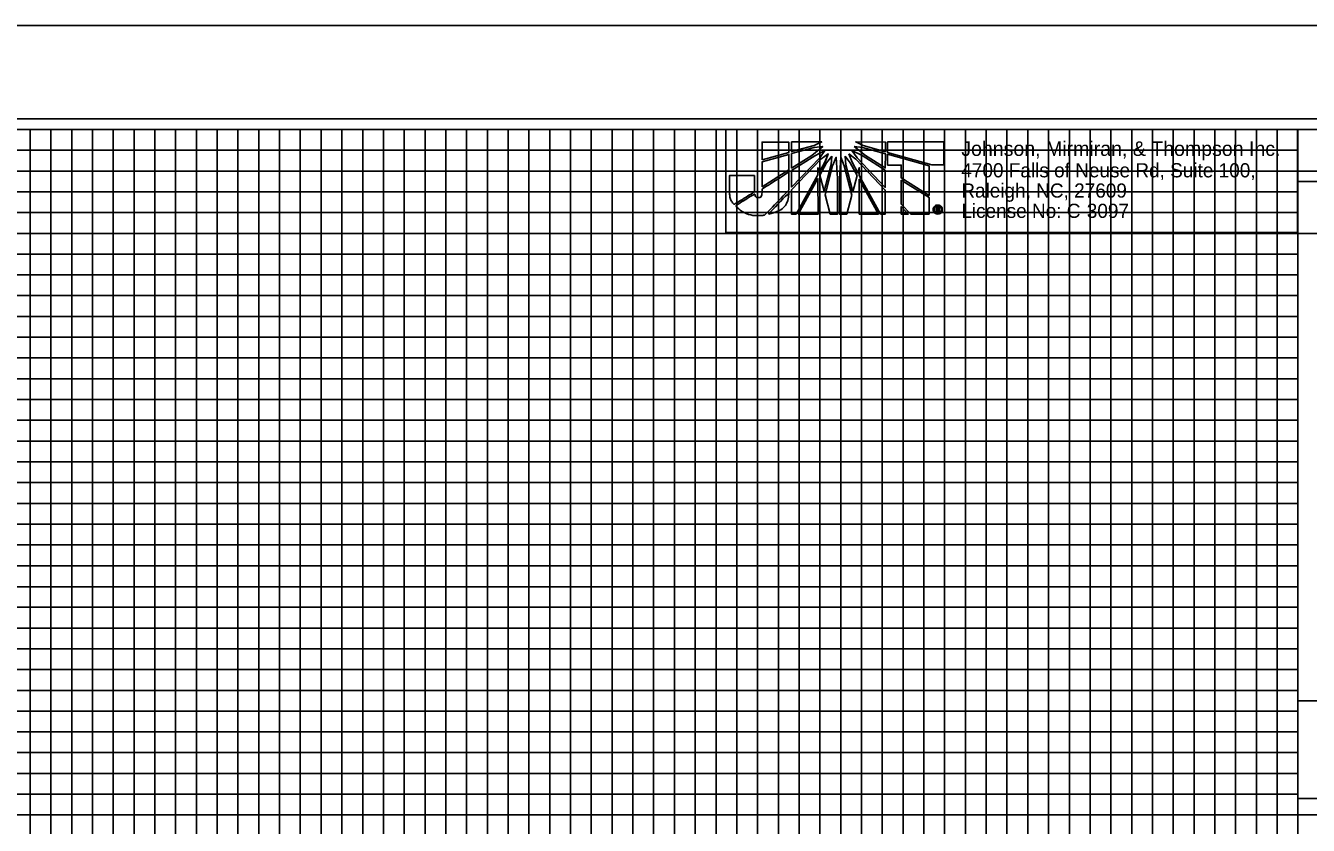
# Model space of a CAD drawing. Extents: x 1623313 to 1628771, y 891211 to 901910.
# Drawn here: x 1624473.9 to 1624782.4, y 901666.9 to 901859.4 of the extents above; entities that cross this region are included whole.
import ezdxf

# ---------------------------------------------------------------- set-up
doc = ezdxf.new("R2010")
doc.units = 0
for name, color, linetype in [('Default', 7, 'Continuous'), ('Prop PHM Black Shape', 7, 'Continuous'), ('Scratch_Level_0', 7, 'Continuous'), ('Sheet Cutting Line CELL', 7, 'Continuous'), ('Sheet DOT Grid CELL', 7, 'Continuous'), ('Sheet Plot Border Inside CELL', 7, 'Continuous'), ('Sheet Plot Border Outside CELL', 7, 'Continuous'), ('Sheet Profile CELL', 7, 'Continuous'), ('Sheet Profile Grid Major CELL', 7, 'Continuous'), ('Sheet Profile Grid Middle CELL', 7, 'Continuous'), ('Sheet Profile Grid Minor CELL', 7, 'Continuous'), ('Sheet Sticker Exception Certification CELL', 7, 'Continuous')]:
    doc.layers.add(name, color=color, linetype=linetype)

msp = doc.modelspace()

# ---------------------------------------------------------------- linework, layer by layer
at = {"layer": 'Default'}
for p, q in [((1624657.46, 901831.41), (1624651.03, 901831.4)), ((1624651.03, 901831.4), (1624651.03, 901827.13)), ((1624657.47, 901828.92), (1624657.46, 901831.41)), ((1624665.38, 901831.45), (1624658.13, 901831.44)), ((1624658.13, 901831.44), (1624658.13, 901829.14)), ((1624663.53, 901830.63), (1624665.38, 901831.45)), ((1624680.71, 901831.43), (1624673.57, 901831.45)), ((1624673.57, 901831.45), (1624675.38, 901830.61)), ((1624680.71, 901829.11), (1624680.71, 901831.43)), ((1624694.74, 901831.47), (1624681.21, 901831.46)), ((1624681.21, 901831.46), (1624681.21, 901828.97)), ((1624694.75, 901825.93), (1624694.74, 901831.47)), ((1624651.03, 901827.13), (1624657.47, 901828.92)), ((1624657.47, 901828.46), (1624651.03, 901826.64)), ((1624657.47, 901824.73), (1624657.47, 901828.46)), ((1624658.13, 901829.14), (1624663.53, 901830.63)), ((1624663.53, 901830.13), (1624658.14, 901828.64)), ((1624658.14, 901828.64), (1624658.14, 901825.15)), ((1624658.14, 901825.15), (1624662.97, 901828.22)), ((1624663.71, 901828.14), (1624658.14, 901824.59)), ((1624662.97, 901828.22), (1624665.63, 901830.38)), ((1624665.63, 901830.38), (1624663.53, 901830.13)), ((1624666.16, 901829.39), (1624663.71, 901828.14)), ((1624664.92, 901827.64), (1624666.16, 901829.39)), ((1624666.91, 901828.61), (1624665.2, 901827.29)), ((1624666.12, 901826.55), (1624666.91, 901828.61)), ((1624667.83, 901828.04), (1624666.56, 901826.4)), ((1624667.65, 901826.05), (1624667.83, 901828.04)), ((1624670.99, 901828.04), (1624671.2, 901825.98)), ((1624672.23, 901826.41), (1624670.99, 901828.04)), ((1624671.9, 901828.62), (1624672.69, 901826.56)), ((1624673.61, 901827.3), (1624671.9, 901828.62)), ((1624672.65, 901829.39), (1624673.9, 901827.62)), ((1624675.14, 901828.15), (1624672.65, 901829.39)), ((1624673.21, 901830.39), (1624675.91, 901828.18)), ((1624675.2, 901830.14), (1624673.21, 901830.39)), ((1624680.67, 901824.64), (1624675.14, 901828.15)), ((1624680.71, 901828.62), (1624675.2, 901830.14)), ((1624675.38, 901830.61), (1624680.71, 901829.11)), ((1624675.91, 901828.18), (1624680.67, 901825.21)), ((1624680.67, 901825.21), (1624680.71, 901828.62)), ((1624681.21, 901828.97), (1624681.21, 901828.9)), ((1624681.21, 901828.9), (1624691.87, 901825.93)), ((1624681.21, 901828.52), (1624681.21, 901828.48)), ((1624691.19, 901825.68), (1624681.21, 901828.52)), ((1624681.21, 901828.48), (1624681.22, 901825.88)), ((1624651.03, 901826.64), (1624651.04, 901820.64)), ((1624651.04, 901820.64), (1624657.47, 901824.73)), ((1624658.14, 901820.58), (1624664.92, 901827.64)), ((1624665.2, 901827.29), (1624658.14, 901819.9)), ((1624664.46, 901823.57), (1624664.46, 901825.26)), ((1624664.46, 901825.26), (1624664.78, 901824.1)), ((1624664.78, 901824.1), (1624666.12, 901826.55)), ((1624666.56, 901826.4), (1624664.96, 901823.49)), ((1624665.99, 901819.63), (1624667.65, 901826.05)), ((1624668.01, 901825.69), (1624666.2, 901818.73)), ((1624668.89, 901827.75), (1624668.01, 901825.69)), ((1624669.17, 901822.68), (1624668.89, 901827.75)), ((1624669.96, 901827.75), (1624669.63, 901822.68)), ((1624670.81, 901825.69), (1624669.96, 901827.75)), ((1624672.66, 901818.63), (1624670.81, 901825.69)), ((1624671.2, 901825.98), (1624672.87, 901819.48)), ((1624673.9, 901823.39), (1624672.23, 901826.41)), ((1624672.69, 901826.56), (1624674.07, 901824)), ((1624680.68, 901819.85), (1624673.61, 901827.3)), ((1624673.9, 901827.62), (1624680.68, 901820.52)), ((1624674.07, 901824), (1624674.4, 901825.27)), ((1624674.4, 901825.27), (1624674.4, 901823.39)), ((1624681.22, 901825.88), (1624684.52, 901825.89)), ((1624684.52, 901825.89), (1624684.52, 901822.8)), ((1624691.19, 901818.58), (1624691.19, 901825.68)), ((1624691.87, 901825.93), (1624694.75, 901825.93)), ((1624658.14, 901824.59), (1624658.14, 901820.58)), ((1624659.21, 901814.06), (1624664.46, 901823.57)), ((1624664.46, 901822.64), (1624659.71, 901814.06)), ((1624664.51, 901814.06), (1624664.46, 901822.64)), ((1624664.96, 901823.49), (1624665.99, 901819.63)), ((1624669.18, 901814.1), (1624669.17, 901822.68)), ((1624669.63, 901822.68), (1624669.64, 901814.1)), ((1624672.87, 901819.48), (1624673.9, 901823.39)), ((1624674.4, 901823.39), (1624679.55, 901814.07)), ((1624679.02, 901814.1), (1624674.4, 901822.47)), ((1624674.4, 901822.47), (1624674.41, 901814.1)), ((1624680.68, 901820.52), (1624680.67, 901824.64)), ((1624684.52, 901822.8), (1624691.19, 901818.58)), ((1624684.52, 901822.27), (1624684.53, 901816.51)), ((1624691.19, 901818.08), (1624684.52, 901822.27)), ((1624658.14, 901819.9), (1624658.15, 901814.05)), ((1624666.2, 901818.73), (1624667.42, 901814.09)), ((1624671.42, 901814.1), (1624672.66, 901818.63)), ((1624680.68, 901814.07), (1624680.68, 901819.85)), ((1624684.53, 901816.51), (1624686.83, 901814.08)), ((1624686.2, 901814.08), (1624684.53, 901815.88)), ((1624684.53, 901815.88), (1624684.53, 901814.08)), ((1624691.2, 901814.08), (1624691.19, 901818.08)), ((1624692.89, 901814.69), (1624692.89, 901815.68)), ((1624692.89, 901815.68), (1624693.29, 901815.68)), ((1624693.29, 901815.49), (1624693.11, 901815.49)), ((1624693.11, 901815.49), (1624693.11, 901815.26)), ((1624693.29, 901816.26), (1624693.29, 901816.05)), ((1624693.29, 901816.05), (1624693.29, 901816.26)), ((1624693.29, 901815.68), (1624693.29, 901815.49)), ((1624693.29, 901815.49), (1624693.29, 901815.68)), ((1624693.29, 901815.68), (1624693.36, 901815.68)), ((1624693.32, 901815.49), (1624693.29, 901815.49)), ((1624658.15, 901814.05), (1624659.21, 901814.06)), ((1624659.71, 901814.06), (1624664.51, 901814.06)), ((1624667.42, 901814.09), (1624669.18, 901814.1)), ((1624669.64, 901814.1), (1624671.42, 901814.1)), ((1624674.41, 901814.1), (1624679.02, 901814.1)), ((1624679.55, 901814.07), (1624680.68, 901814.07)), ((1624684.53, 901814.08), (1624686.2, 901814.08)), ((1624686.83, 901814.08), (1624691.2, 901814.08)), ((1624693.12, 901814.69), (1624692.89, 901814.69)), ((1624693.11, 901815.26), (1624693.29, 901815.26)), ((1624693.29, 901815.08), (1624693.12, 901815.08)), ((1624693.12, 901815.08), (1624693.12, 901814.69)), ((1624693.29, 901815.26), (1624693.29, 901815.08)), ((1624693.29, 901815.08), (1624693.29, 901815.26)), ((1624693.29, 901815.26), (1624693.3, 901815.26)), ((1624693.3, 901815.08), (1624693.29, 901815.08)), ((1624693.29, 901814.31), (1624693.29, 901814.09)), ((1624693.29, 901814.09), (1624693.29, 901814.31)), ((1624693.29, 901814.31), (1624693.3, 901814.31)), ((1624693.3, 901814.09), (1624693.29, 901814.09))]:
    msp.add_line(p, q, dxfattribs=at)
for points in [[(1624642.32, 901809.63), (1624779.85, 901809.62), (1624779.85, 901834.43), (1624642.32, 901834.45)], [(1624673.57, 901831.45), (1624680.71, 901831.43), (1624680.71, 901829.11), (1624675.38, 901830.61)], [(1624658.15, 901814.05), (1624658.14, 901819.9), (1624665.2, 901827.29), (1624666.91, 901828.61), (1624666.34, 901826.98), (1624664.78, 901824.1), (1624664.46, 901825.26), (1624664.46, 901823.57), (1624659.21, 901814.06)]]:
    msp.add_lwpolyline(points, close=True, dxfattribs=at)
for points in [[(1624651.03, 901827.13), (1624657.47, 901828.92), (1624657.46, 901831.41), (1624651.03, 901831.4), (1624651.03, 901827.13)], [(1624663.53, 901830.63), (1624665.38, 901831.45), (1624658.13, 901831.44), (1624658.13, 901829.14), (1624663.53, 901830.63)], [(1624675.38, 901830.61), (1624680.71, 901829.11), (1624680.71, 901831.43), (1624673.57, 901831.45), (1624675.38, 901830.61)], [(1624694.74, 901831.47), (1624681.21, 901831.46), (1624681.21, 901828.97), (1624681.21, 901828.9), (1624691.87, 901825.93), (1624694.75, 901825.93), (1624694.74, 901831.47)], [(1624651.04, 901820.64), (1624657.47, 901824.73), (1624657.47, 901828.46), (1624651.03, 901826.64), (1624651.04, 901820.64)], [(1624658.14, 901828.64), (1624658.14, 901825.15), (1624662.97, 901828.22), (1624665.63, 901830.38), (1624663.53, 901830.13), (1624658.14, 901828.64)], [(1624658.14, 901824.59), (1624658.14, 901820.58), (1624664.92, 901827.64), (1624666.16, 901829.39), (1624663.71, 901828.14), (1624658.14, 901824.59)], [(1624666.91, 901828.61), (1624665.2, 901827.29), (1624658.14, 901819.9), (1624658.15, 901814.05), (1624659.21, 901814.06), (1624664.46, 901823.57), (1624664.46, 901825.26), (1624664.78, 901824.1), (1624666.12, 901826.55), (1624666.91, 901828.61)], [(1624667.83, 901828.04), (1624666.56, 901826.4), (1624664.96, 901823.49), (1624665.99, 901819.63), (1624667.65, 901826.05), (1624667.83, 901828.04)], [(1624670.99, 901828.04), (1624671.2, 901825.98), (1624672.87, 901819.48), (1624673.9, 901823.39), (1624672.23, 901826.41), (1624670.99, 901828.04)], [(1624671.9, 901828.62), (1624672.69, 901826.56), (1624674.07, 901824), (1624674.4, 901825.27), (1624674.4, 901823.39), (1624679.55, 901814.07), (1624680.68, 901814.07), (1624680.68, 901819.85), (1624673.61, 901827.3), (1624671.9, 901828.62)], [(1624672.65, 901829.39), (1624673.9, 901827.62), (1624680.68, 901820.52), (1624680.67, 901824.64), (1624675.14, 901828.15), (1624672.65, 901829.39)], [(1624673.21, 901830.39), (1624675.91, 901828.18), (1624680.67, 901825.21), (1624680.71, 901828.62), (1624675.2, 901830.14), (1624673.21, 901830.39)], [(1624681.21, 901828.52), (1624681.21, 901828.48), (1624681.22, 901825.88), (1624684.52, 901825.89), (1624684.52, 901822.8), (1624691.19, 901818.58), (1624691.19, 901825.68), (1624681.21, 901828.52)], [(1624668.01, 901825.69), (1624666.2, 901818.73), (1624667.42, 901814.09), (1624669.18, 901814.1), (1624669.17, 901822.68), (1624668.89, 901827.75), (1624668.01, 901825.69)], [(1624669.96, 901827.75), (1624669.63, 901822.68), (1624669.64, 901814.1), (1624671.42, 901814.1), (1624672.66, 901818.63), (1624670.81, 901825.69), (1624669.96, 901827.75)], [(1624659.71, 901814.06), (1624664.51, 901814.06), (1624664.46, 901822.64), (1624659.71, 901814.06)], [(1624674.41, 901814.1), (1624679.02, 901814.1), (1624674.4, 901822.47), (1624674.41, 901814.1)], [(1624684.52, 901822.27), (1624684.53, 901816.51), (1624686.83, 901814.08), (1624691.2, 901814.08), (1624691.19, 901818.08), (1624684.52, 901822.27), (1624684.52, 901822.27)], [(1624684.53, 901814.08), (1624684.53, 901814.08), (1624686.2, 901814.08), (1624684.53, 901815.88), (1624684.53, 901814.08)], [(1624693.72, 901814.93), (1624693.72, 901814.87), (1624693.73, 901814.84), (1624693.73, 901814.8), (1624693.76, 901814.69), (1624693.55, 901814.69)]]:
    msp.add_lwpolyline(points, dxfattribs=at)
for points, degree in [([(1624649.19, 901823.4), (1624649.19, 901823.4), (1624643.23, 901823.4), (1624643.23, 901823.4), (1624643.23, 901823.4), (1624643.23, 901819.67), (1624643.23, 901819.67), (1624643.23, 901819.67), (1624643.23, 901819.28), (1624643.23, 901819.28), (1624643.23, 901818.11), (1624643.62, 901817.19), (1624644.3, 901816.41), (1624644.3, 901816.41), (1624649.19, 901819.39), (1624649.19, 901819.46), (1624649.19, 901819.46), (1624649.19, 901823.4), (1624649.19, 901823.4)], 3), ([(1624650.12, 901818.04), (1624649.73, 901818.04), (1624649.4, 901818.25), (1624649.26, 901818.96), (1624649.26, 901818.96), (1624644.65, 901816.1), (1624644.65, 901816.1), (1624646.07, 901814.61), (1624648.35, 901813.72), (1624650.27, 901813.72), (1624650.77, 901813.72), (1624651.15, 901813.76), (1624651.68, 901813.87), (1624651.68, 901813.87), (1624657.47, 901819.86), (1624657.47, 901819.86), (1624657.47, 901819.86), (1624657.47, 901824.2), (1624657.47, 901824.2), (1624657.47, 901824.2), (1624651.04, 901820.1), (1624651.04, 901820.1), (1624651.04, 901818.48), (1624650.65, 901818.04), (1624650.12, 901818.04)], 3), ([(1624650.12, 901818.04), (1624649.73, 901818.04), (1624649.4, 901818.25), (1624649.26, 901818.96), (1624649.26, 901818.96), (1624644.65, 901816.1), (1624644.65, 901816.1), (1624646.07, 901814.61), (1624648.35, 901813.72), (1624650.27, 901813.72), (1624650.77, 901813.72), (1624651.15, 901813.76), (1624651.68, 901813.87), (1624651.68, 901813.87), (1624657.47, 901819.86), (1624657.47, 901819.86), (1624657.47, 901819.86), (1624657.47, 901824.2), (1624657.47, 901824.2), (1624657.47, 901824.2), (1624651.04, 901820.1), (1624651.04, 901820.1), (1624651.04, 901818.48), (1624650.65, 901818.04), (1624650.12, 901818.04)], 3), ([(1624657.47, 901819.18), (1624657.47, 901819.18), (1624652.47, 901814.01), (1624652.47, 901814.01), (1624654.92, 901814.61), (1624657.36, 901816.24), (1624657.47, 901819.18)], 3), ([(1624693.29, 901814.09), (1624693, 901814.09), (1624692.74, 901814.2), (1624692.53, 901814.41), (1624692.31, 901814.62), (1624692.2, 901814.88), (1624692.2, 901815.18), (1624692.2, 901815.49), (1624692.31, 901815.75), (1624692.52, 901815.94), (1624692.74, 901816.15), (1624692.99, 901816.26), (1624693.29, 901816.26)], 3), ([(1624693.29, 901816.05), (1624693.05, 901816.05), (1624692.85, 901815.97), (1624692.68, 901815.81), (1624692.51, 901815.64), (1624692.42, 901815.43), (1624692.42, 901815.18), (1624692.42, 901814.94), (1624692.51, 901814.73), (1624692.68, 901814.56), (1624692.85, 901814.39), (1624693.05, 901814.31), (1624693.29, 901814.31)], 3), ([(1624693.29, 901816.26), (1624693.6, 901816.26), (1624693.86, 901816.15), (1624694.07, 901815.95), (1624694.29, 901815.75), (1624694.39, 901815.49), (1624694.39, 901815.19)], 3), ([(1624693.3, 901814.31), (1624693.55, 901814.31), (1624693.75, 901814.39), (1624693.92, 901814.56), (1624694.09, 901814.73), (1624694.18, 901814.94), (1624694.18, 901815.18), (1624694.18, 901815.43), (1624694.09, 901815.64), (1624693.92, 901815.81), (1624693.75, 901815.97), (1624693.54, 901816.05), (1624693.29, 901816.05)], 3), ([(1624693.3, 901815.26), (1624693.45, 901815.26), (1624693.52, 901815.3), (1624693.52, 901815.38), (1624693.52, 901815.45), (1624693.45, 901815.49), (1624693.32, 901815.49)], 3), ([(1624693.36, 901815.68), (1624693.61, 901815.68), (1624693.73, 901815.58), (1624693.73, 901815.38), (1624693.73, 901815.29), (1624693.7, 901815.22), (1624693.62, 901815.17)], 3), ([(1624694.39, 901815.19), (1624694.39, 901814.88), (1624694.29, 901814.62), (1624694.08, 901814.41), (1624693.87, 901814.2), (1624693.61, 901814.09), (1624693.3, 901814.09)], 3), ([(1624693.47, 901815.04), (1624693.45, 901815.06), (1624693.39, 901815.08), (1624693.3, 901815.08)], 2), ([(1624693.55, 901814.69), (1624693.53, 901814.75), (1624693.51, 901814.8), (1624693.51, 901814.87), (1624693.51, 901814.96), (1624693.5, 901815.01), (1624693.47, 901815.04)], 3), ([(1624693.62, 901815.17), (1624693.68, 901815.13), (1624693.71, 901815.05), (1624693.72, 901814.93)], 2)]:
    msp.add_open_spline(points, degree=degree, dxfattribs=at)
at = {"layer": 'Prop PHM Black Shape'}
msp.add_lwpolyline([(1624642.32, 901834.45), (1624779.85, 901834.45), (1624779.85, 901809.62), (1624642.32, 901809.62)], close=True, dxfattribs=at)
at = {"layer": 'Scratch_Level_0'}
msp.add_lwpolyline([(1623529.95, 901824.45), (1624929.95, 901824.45), (1624929.95, 901334.45), (1623529.95, 901334.45)], close=True, dxfattribs=at)
at = {"layer": 'Sheet Cutting Line CELL'}
msp.add_line((1624996.95, 901859.45), (1623312.95, 901859.45), dxfattribs=at)
at = {"layer": 'Sheet DOT Grid CELL'}
for p, q in [((1624479.95, 901334.45), (1624479.95, 901834.45)), ((1624529.95, 901334.45), (1624529.95, 901834.45)), ((1624579.95, 901334.45), (1624579.95, 901834.45)), ((1624629.95, 901334.45), (1624629.95, 901834.45)), ((1624679.95, 901334.45), (1624679.95, 901834.45)), ((1624729.95, 901334.45), (1624729.95, 901834.45)), ((1624779.9, 901784.45), (1623479.95, 901784.45)), ((1624779.9, 901734.45), (1623479.95, 901734.45)), ((1624779.95, 901334.45), (1624779.95, 901696.9)), ((1624779.95, 901684.45), (1623479.95, 901684.45))]:
    msp.add_line(p, q, dxfattribs=at)
at = {"layer": 'Sheet Plot Border Inside CELL'}
msp.add_lwpolyline([(1623325.95, 900781.9), (1624992.45, 900781.9), (1624992.45, 901837), (1623325.95, 901837)], close=True, dxfattribs=at)
at = {"layer": 'Sheet Plot Border Outside CELL'}
msp.add_lwpolyline([(1623312.95, 900759.45), (1624996.95, 900759.45), (1624996.95, 901859.45), (1623312.95, 901859.45)], close=True, dxfattribs=at)
at = {"layer": 'Sheet Profile CELL'}
msp.add_line((1624779.9, 901821.9), (1624979.95, 901821.9), dxfattribs=at)
for points in [[(1624979.95, 901834.45), (1623479.95, 901834.45), (1623479.95, 900784.45), (1624979.95, 900784.45)], [(1624779.9, 901834.45), (1624979.95, 901834.45), (1624979.95, 901809.4), (1624779.9, 901809.4)], [(1624779.9, 901809.4), (1624879.95, 901809.4), (1624879.95, 901696.9), (1624779.9, 901696.9)]]:
    msp.add_lwpolyline(points, close=True, dxfattribs=at)
at = {"layer": 'Sheet Profile Grid Major CELL'}
for points in [[(1624429.95, 901334.45), (1624479.95, 901334.45), (1624479.95, 901834.45), (1624529.95, 901834.45), (1624529.95, 901334.45), (1624579.95, 901334.45), (1624579.95, 901834.45), (1624629.95, 901834.45), (1624629.95, 901334.45), (1624679.95, 901334.45), (1624679.95, 901834.45), (1624729.95, 901834.45), (1624729.95, 901334.45), (1624779.95, 901334.45), (1624779.95, 901834.45), (1624806.25, 901834.45)], [(1623479.95, 901784.45), (1624779.95, 901784.45)], [(1624779.95, 901734.45), (1623479.95, 901734.45), (1623479.95, 901684.45), (1624779.95, 901684.45)]]:
    msp.add_lwpolyline(points, dxfattribs=at)
at = {"layer": 'Sheet Profile Grid Middle CELL'}
msp.add_line((1623479.95, 901809.45), (1624779.9, 901809.45), dxfattribs=at)
for points in [[(1624454.95, 901334.45), (1624504.95, 901334.45), (1624504.95, 901834.45), (1624554.95, 901834.45), (1624554.95, 901334.45), (1624604.95, 901334.45), (1624604.95, 901834.45), (1624654.95, 901834.45), (1624654.95, 901334.45), (1624704.95, 901334.45), (1624704.95, 901834.45), (1624754.95, 901834.45), (1624754.95, 901334.45), (1624804.95, 901334.45)], [(1624779.95, 901759.45), (1623479.95, 901759.45), (1623479.95, 901709.45), (1624779.95, 901709.45)]]:
    msp.add_lwpolyline(points, dxfattribs=at)
at = {"layer": 'Sheet Profile Grid Minor CELL'}
for p, q in [((1624624.9, 901834.45), (1624634.9, 901834.45)), ((1624639.9, 901834.45), (1624644.9, 901834.45)), ((1624649.9, 901834.45), (1624659.9, 901834.45)), ((1624664.9, 901834.45), (1624669.9, 901834.45)), ((1623529.95, 901829.45), (1624779.95, 901829.45)), ((1624779.95, 901824.45), (1623529.95, 901824.1)), ((1623529.95, 901819.45), (1624779.95, 901819.45)), ((1624779.9, 901699.45), (1623529.95, 901699.45)), ((1624779.95, 901694.45), (1623529.95, 901694.45)), ((1624779.95, 901689.45), (1623529.95, 901689.45)), ((1623529.95, 901679.45), (1624779.95, 901679.45)), ((1624779.95, 901674.45), (1623529.95, 901674.45)), ((1623529.95, 901669.45), (1624929.95, 901669.45))]:
    msp.add_line(p, q, dxfattribs=at)
for points in [[(1624474.95, 901334.45), (1624474.95, 901834.45), (1624484.95, 901834.45), (1624484.95, 901334.45)], [(1624489.95, 901334.45), (1624489.95, 901834.45), (1624494.95, 901834.45), (1624494.95, 901334.45)], [(1624499.95, 901334.45), (1624499.95, 901834.45), (1624509.95, 901834.45), (1624509.95, 901334.45)], [(1624514.95, 901334.45), (1624514.95, 901834.45), (1624519.95, 901834.45), (1624519.95, 901334.45)], [(1624524.95, 901334.45), (1624524.95, 901834.45), (1624534.95, 901834.45), (1624534.95, 901334.45)], [(1624539.95, 901334.45), (1624539.95, 901834.45), (1624544.95, 901834.45), (1624544.95, 901334.45)], [(1624549.95, 901334.45), (1624549.95, 901834.45), (1624559.95, 901834.45), (1624559.95, 901334.45)], [(1624564.95, 901334.45), (1624564.95, 901834.45), (1624569.95, 901834.45), (1624569.95, 901334.45)], [(1624574.95, 901334.45), (1624574.95, 901834.45), (1624584.95, 901834.45), (1624584.95, 901334.45)], [(1624589.95, 901334.45), (1624589.95, 901834.45), (1624594.95, 901834.45), (1624594.95, 901334.45)], [(1624599.95, 901334.45), (1624599.95, 901834.45), (1624609.95, 901834.45), (1624609.95, 901334.45)], [(1624614.95, 901334.45), (1624614.95, 901834.45), (1624619.95, 901834.45), (1624619.95, 901334.45)], [(1624624.95, 901334.45), (1624624.95, 901834.45), (1624634.95, 901834.45), (1624634.95, 901334.45)], [(1624639.95, 901334.45), (1624639.95, 901834.45), (1624644.95, 901834.45), (1624644.95, 901334.45)], [(1624649.95, 901334.45), (1624649.95, 901834.45), (1624659.95, 901834.45), (1624659.95, 901334.45)], [(1624664.95, 901334.45), (1624664.95, 901834.45), (1624669.95, 901834.45), (1624669.95, 901334.45)], [(1624674.95, 901334.45), (1624674.95, 901834.45), (1624684.95, 901834.45), (1624684.95, 901334.45)], [(1624689.95, 901334.45), (1624689.95, 901834.45), (1624694.95, 901834.45), (1624694.95, 901334.45)], [(1624699.95, 901334.45), (1624699.95, 901834.45), (1624709.95, 901834.45), (1624709.95, 901334.45)], [(1624714.95, 901334.45), (1624714.95, 901834.45), (1624719.95, 901834.45), (1624719.95, 901334.45)], [(1624724.95, 901334.45), (1624724.95, 901834.45), (1624734.95, 901834.45), (1624734.95, 901334.45)], [(1624739.95, 901334.45), (1624739.95, 901834.45), (1624744.95, 901834.45), (1624744.95, 901334.45)], [(1624749.95, 901334.45), (1624749.95, 901834.45), (1624759.95, 901834.45), (1624759.95, 901334.45)], [(1624764.95, 901334.45), (1624764.95, 901834.45), (1624769.95, 901834.45), (1624769.95, 901334.45)], [(1624774.95, 901334.45), (1624774.95, 901834.45), (1624784.95, 901834.45)], [(1624779.95, 901814.45), (1623529.95, 901814.45), (1623529.95, 901804.45), (1624779.95, 901804.45)], [(1624779.9, 901799.45), (1623529.95, 901799.45), (1623529.95, 901794.45), (1624779.95, 901794.45)], [(1624779.95, 901789.45), (1623529.95, 901789.45), (1623529.95, 901779.45), (1624779.95, 901779.45)], [(1624779.95, 901774.45), (1623529.95, 901774.45), (1623529.95, 901769.45), (1624779.95, 901769.45)], [(1624779.95, 901764.45), (1623529.95, 901764.45), (1623529.95, 901754.45), (1624779.95, 901754.45)], [(1624779.95, 901749.45), (1623529.95, 901749.45), (1623529.95, 901744.45), (1624779.95, 901744.45)], [(1624779.95, 901739.45), (1623529.95, 901739.45), (1623529.95, 901729.45), (1624779.95, 901729.45)], [(1624779.95, 901724.35), (1623530.05, 901724.35), (1623530.05, 901719.45), (1624779.95, 901719.45)], [(1624779.95, 901714.45), (1623529.95, 901714.45), (1623529.95, 901704.45), (1624779.95, 901704.45)]]:
    msp.add_lwpolyline(points, dxfattribs=at)
at = {"layer": 'Sheet Sticker Exception Certification CELL'}
for p, q in [((1624779.9, 901673.4), (1624779.9, 901696.9)), ((1624779.9, 901696.9), (1624979.93, 901696.9)), ((1624779.9, 901673.4), (1624779.9, 901696.9)), ((1624779.9, 901696.9), (1624979.93, 901696.9)), ((1624979.93, 901673.4), (1624779.9, 901673.4)), ((1624979.93, 901673.4), (1624779.9, 901673.4))]:
    msp.add_line(p, q, dxfattribs=at)

# ---------------------------------------------------------------- texts
at = {"layer": 'Default'}
for s, height, p in [('Johnson, Mirmiran, & Thompson Inc.', 3.5139, (1624698.96, 901828.09)), ('4700 Falls of Neuse Rd, Suite 100, ', 3.4135, (1624698.96, 901822.93)), ('Raleigh, NC, 27609', 3.4135, (1624698.96, 901818.05)), ('License No: C-3097', 3.4135, (1624698.96, 901813.17))]:
    msp.add_text(s, height=height, rotation=359.9946, dxfattribs=at).set_placement(p)

doc.saveas('drawing.dxf')
